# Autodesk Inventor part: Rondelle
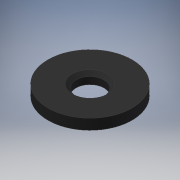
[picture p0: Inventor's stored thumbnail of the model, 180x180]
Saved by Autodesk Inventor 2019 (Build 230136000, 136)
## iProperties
Created: 2018-06
Part Number: Rondelle
Material: Caoutchouc
Document SubType Name: Modeling
Designer: Fabian Perrée
Density: 0.93 g/cm^3
Appearance: Caoutchouc - Noir
Author: Fabian Perrée
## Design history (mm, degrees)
sketch "Esquisse1"
  geometry: C1 r 6 at (0, 0); C2 r 2 at (0, 0); 1 further point
  constraints: 2 centre point, 2 coincident
  dimensions: "d0" = 12 diameter of C1; "d1" = 4 diameter of C2
extrude "Extrusion1" new body sketch "Esquisse1" distance "d2" = 1.5; taper "d3" = 0 deg
chamfer "Chanfrein1" distance "d4" = 0.5; stored, may be unused: second distance "d5" = 2, angle "d6" = 45 deg
node "Solide1"
